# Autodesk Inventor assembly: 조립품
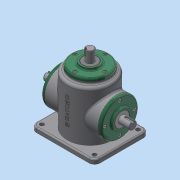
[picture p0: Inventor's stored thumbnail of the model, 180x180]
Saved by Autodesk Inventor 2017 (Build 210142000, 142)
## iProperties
Part Number: 조립품
Material: 일반
Document SubType Name: Assembly
Designer: MRC
Author: MRC
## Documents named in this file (16)
- C:\Users\MRC\Desktop\710116V1008\조립품.iam
- C:\Users\MRC\Desktop\710116V1008\본체.ipt
- C:\Users\MRC\Desktop\710116V1008\메인 베벨기어.ipt
- C:\Users\MRC\Desktop\710116V1008\메인 축.ipt
- 메인 축.ipt
- C:\Users\MRC\Desktop\710116V1008\베어링 6203.ipt
- C:\Users\MRC\Desktop\710116V1008\볼트 M4.ipt
- 볼트 M4.ipt
- C:\Users\MRC\Desktop\710116V1008\서브 베벨기어.ipt
- C:\Users\MRC\Desktop\710116V1008\서브 축.ipt
- 서브 축.ipt
- C:\Users\MRC\Desktop\710116V1008\오일 실.ipt
- 오일 실.ipt
- C:\Users\MRC\Desktop\710116V1008\커버.ipt
- C:\Users\MRC\Desktop\710116V1008\키 4x4.ipt
- C:\Users\MRC\Desktop\710116V1008\키 5x5.ipt
